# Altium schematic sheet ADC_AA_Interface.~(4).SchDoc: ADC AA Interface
size B; Engineer: J. Heefner; DocumentNumber: D070100; Revision: 01; SheetNumber: 1; SheetTotal: 1; PageSetup: Record=PageOptions¦CenterHorizontal=True¦CenterVertical=True¦PrintScale=0.52¦XCorrection=1.00¦YCorrection=1.00¦PrintKind=0¦BorderSize=5000000¦LeftOffset=0¦BottomOffset=0¦Orientation=2¦PaperLength=4318¦PaperWidth=2794¦Scale=100¦PaperSource=15¦PrintQuality=1200¦MediaType=1¦DitherType=10¦PaperKind=Tabloid¦PrintScaleMode=1
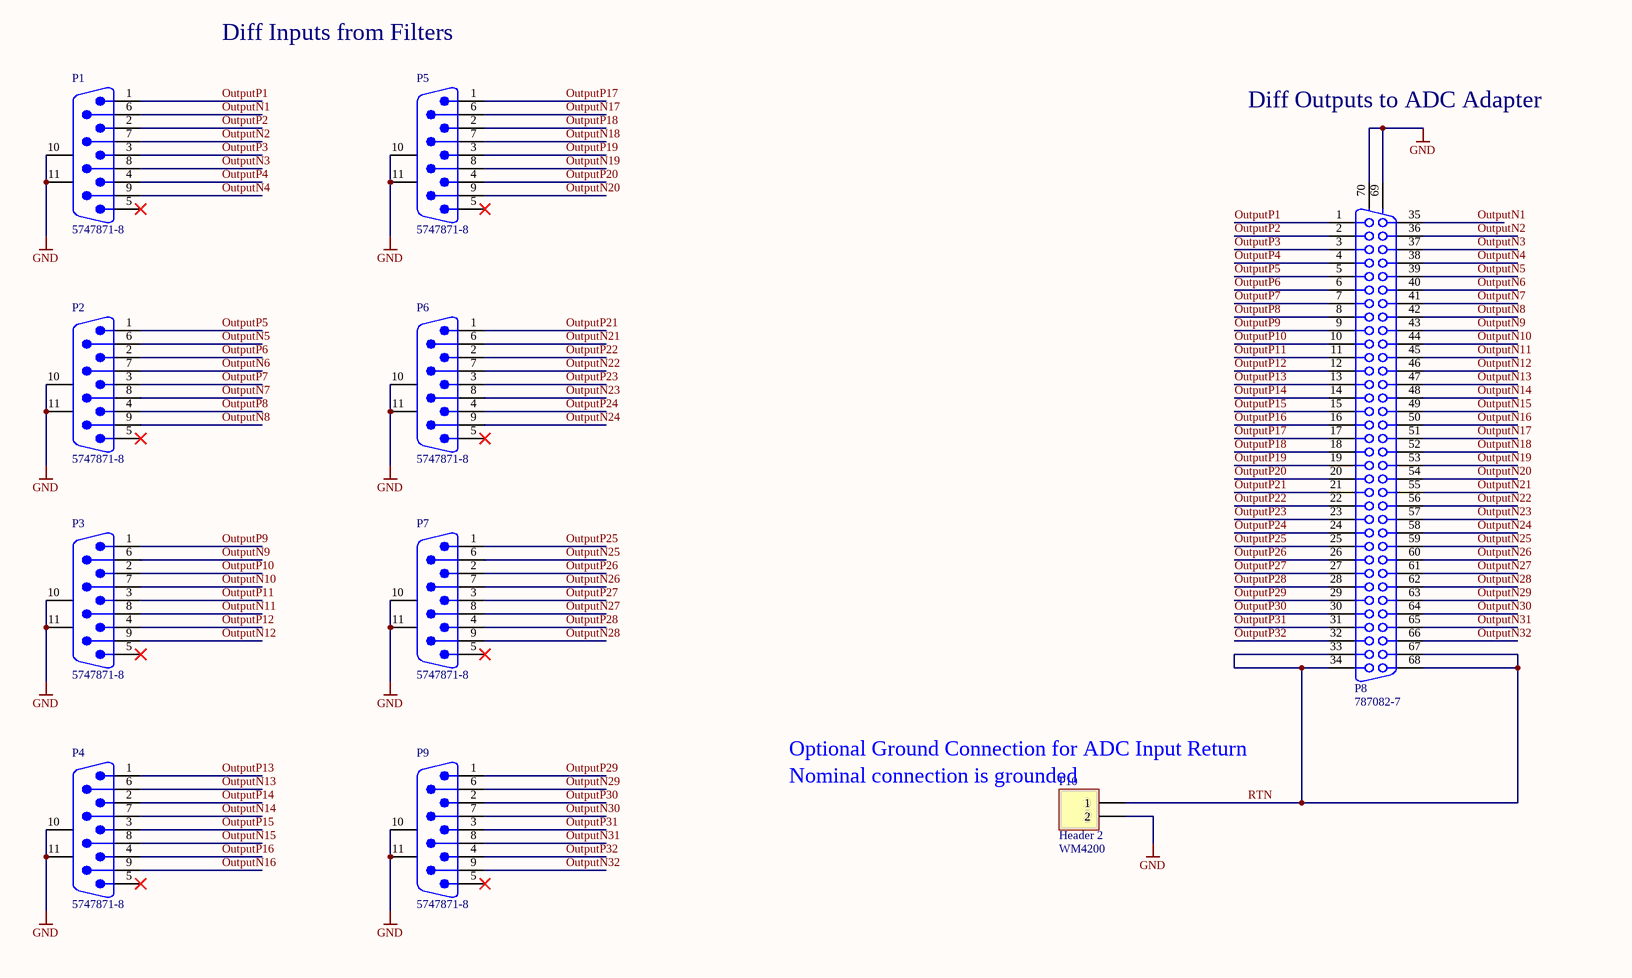
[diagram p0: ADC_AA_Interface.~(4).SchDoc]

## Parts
P1  5747871-8  [DB9/M]
P2  5747871-8  [DB9/M]
P3  5747871-8  [DB9/M]
P4  5747871-8  [DB9/M]
P5  5747871-8  [DB9/M]
P6  5747871-8  [DB9/M]
P7  5747871-8  [DB9/M]
P8  787082-7  [787082-7]
P9  5747871-8  [DB9/M]
P10  Header 2  Part Number: WM4200  [HDR1X2]

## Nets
GND: P1.10(MH1) P1.11(MH2) P2.10(MH1) P2.11(MH2) P3.10(MH1) P3.11(MH2) P4.10(MH1) P4.11(MH2) P5.10(MH1) P5.11(MH2) P6.10(MH1) P6.11(MH2) P7.10(MH1) P7.11(MH2) P8.69(MH1) P8.70(MH2) P9.10(MH1) P9.11(MH2) P10.2
OutputN1: P1.6 P8.35
OutputN2: P1.7 P8.36
OutputN3: P1.8 P8.37
OutputN4: P1.9 P8.38
OutputN5: P2.6 P8.39
OutputN6: P2.7 P8.40
OutputN7: P2.8 P8.41
OutputN8: P2.9 P8.42
OutputN9: P3.6 P8.43
OutputN10: P3.7 P8.44
OutputN11: P3.8 P8.45
OutputN12: P3.9 P8.46
OutputN13: P4.6 P8.47
OutputN14: P4.7 P8.48
OutputN15: P4.8 P8.49
OutputN16: P4.9 P8.50
OutputN17: P5.6 P8.51
OutputN18: P5.7 P8.52
OutputN19: P5.8 P8.53
OutputN20: P5.9 P8.54
OutputN21: P6.6 P8.55
OutputN22: P6.7 P8.56
OutputN23: P6.8 P8.57
OutputN24: P6.9 P8.58
OutputN25: P7.6 P8.59
OutputN26: P7.7 P8.60
OutputN27: P7.8 P8.61
OutputN28: P7.9 P8.62
OutputN29: P8.63 P9.6
OutputN30: P8.64 P9.7
OutputN31: P8.65 P9.8
OutputN32: P8.66 P9.9
OutputP1: P1.1 P8.1
OutputP2: P1.2 P8.2
OutputP3: P1.3 P8.3
OutputP4: P1.4 P8.4
OutputP5: P2.1 P8.5
OutputP6: P2.2 P8.6
OutputP7: P2.3 P8.7
OutputP8: P2.4 P8.8
OutputP9: P3.1 P8.9
OutputP10: P3.2 P8.10
OutputP11: P3.3 P8.11
OutputP12: P3.4 P8.12
OutputP13: P4.1 P8.13
OutputP14: P4.2 P8.14
OutputP15: P4.3 P8.15
OutputP16: P4.4 P8.16
OutputP17: P5.1 P8.17
OutputP18: P5.2 P8.18
OutputP19: P5.3 P8.19
OutputP20: P5.4 P8.20
OutputP21: P6.1 P8.21
OutputP22: P6.2 P8.22
OutputP23: P6.3 P8.23
OutputP24: P6.4 P8.24
OutputP25: P7.1 P8.25
OutputP26: P7.2 P8.26
OutputP27: P7.3 P8.27
OutputP28: P7.4 P8.28
OutputP29: P8.29 P9.1
OutputP30: P8.30 P9.2
OutputP31: P8.31 P9.3
OutputP32: P8.32 P9.4
RTN: P8.33 P8.34 P8.67 P8.68 P10.1

Not connected (* = marked no-connect by the designer): P1 5*; P2 5*; P3 5*; P4 5*; P5 5*; P6 5*; P7 5*; P9 5*

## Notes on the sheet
- Diff Inputs from Filters
- Diff Outputs to ADC Adapter
- (near P10) Optional Ground Connection for ADC Input Return
- (near P10) Nominal connection is grounded

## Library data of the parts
P1-P7 P9 = 788754-1: 9 Position D-Sub Plug, Male Pins Connector; Manufacturer: TE Connectivity; Description: CONN D-SUB PLUG 9POS VERT SOLDER; Plating: Tin; Body Material: Steel; Voltage Rating: 125V; Current Rating: 6A; Max Voltage Rating (DC): 250.25kV; Number of Positions: 9; Number of Ports: 1; Max Supply Voltage (AC): 250V; Mating Connector Lock: Yes (With); PCB Mount Retention: With; PCB Mounting Orientation: Vertical; Preloaded: Yes; Sealable: No (Without); Pitch: 0.108inch; PCB Thickness: 2.36mm; Contact Post Length: 0.125inch; Hole Diameter: 0.12inch; Approvals: UL
P8 = 787082-7: Receptacle Assembly, Shielded, Right Angle, AMPLIMITE; Positions: 68; Note: Series III; Gender: Receptacle Header; Note: With Mating Lock; PCB_Layout: Complies with manufacturer's recommendation.; DrillSize: Corresponds to nominal value.
P10 = Header 2: Header, 2-Pin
